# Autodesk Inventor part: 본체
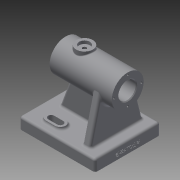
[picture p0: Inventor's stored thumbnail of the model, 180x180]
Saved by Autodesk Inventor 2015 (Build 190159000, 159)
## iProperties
Created: 2022-06
Part Number: 본체
Material: 일반
Document SubType Name: Modeling
Designer: 104658
Density: 1 g/cm^3
Appearance: 기본값
Author: 104658
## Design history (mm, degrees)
sketch "스케치1"
  geometry: L1 (-50, -43)-(50, -43); L2 (50, -43)-(50, 43); L3 (50, 43)-(-50, 43); L4 (-50, 43)-(-50, -43); L5 (-50, -43)-(50, 43); L6 (50, -43)-(-50, 43); 1 further point
  constraints: 12 end point, 2 midpoint, 2 parallel, 1 horizontal, 1 perpendicular
  dimensions: "d0" = 100 distance of L2.end L3.end; "d1" = 86 distance of L1.end L2.end
extrude "돌출1" new body sketch "스케치1" distance "d2" = 15; taper "d3" = 0 deg
sketch "스케치2"
  geometry: L1 (-50, -43)-(50, -43) reference; L2 (50, -43)-(50, 43) reference; L3 (50, 43)-(-50, 43) reference; L4 (-50, 43)-(-50, -43) reference; L5 (25, -35)-(35, -35); L6 (35, -35)-(35, 35); L7 (35, 35)-(25, 35); L8 (25, 35)-(25, -35); L9 (25, -35)-(35, 35); L10 (35, -35)-(25, 35); L11 (-35, -5)-(35, -5); L12 (35, -5)-(35, 5); L13 (35, 5)-(-35, 5); L14 (-35, 5)-(-35, -5); L15 (-35, -5)-(35, 5); L16 (35, -5)-(-35, 5); 3 further points
  constraints: 24 end point, 4 midpoint, 4 parallel, 2 horizontal, 2 perpendicular, 1 point on line
  dimensions: "d4" = 15 distance between parallel lines of L2 L6; "d5" = 10 distance of L6.end L7.end; "d6" = 10 distance of L13.end L11.start; "d7" = 43 distance from line of L1 point (0, 0); "d8" = 15 distance between parallel lines of L4 L14; "d9" = 8 distance between parallel lines of L1 L5; "d10" = 8 distance between parallel lines of L3 L7
extrude "돌출2" join sketch "스케치2" distance "d11" = 57; taper "d12" = 0 deg
feature "면 기울기1" dims angle "d13" = 20 deg
sketch "스케치3"
  geometry: L1 (-50, 0)-(-50, 15) reference; L2 (-50, 15)-(-35, 15) reference; L3 (-35, 15)-(-35, 72) reference; L4 (-35, 72)-(14.254, 72) reference; L5 (14.254, 72)-(35, 15) reference; L6 (35, 15)-(50, 15) reference; L7 (50, 15)-(50, 0) reference; L8 (50, 0)-(-50, 0) reference; L9 (-50, 93)-(32, 93); L10 (32, 93)-(32, 72); L11 (32, 72)-(-50, 72); L12 (-50, 72)-(-50, 93); 1 further point
  constraints: 8 end point, 2 parallel, 1 collinear, 1 horizontal, 1 perpendicular, 1 vertical alignment
  dimensions: "d14" = 21 distance of L11.end L9.start; "d15" = 82 distance of L9.start L9.end
revolve "회전1" sketch "스케치3" stored, may be unused: angle "d16" = 90 deg
sketch "스케치4"
  geometry: L1 (-57, 0)-(-57, 14) reference; L2 (15, -8)-(0, -8) reference; L3 (0, -8)-(0, 0) reference; L4 (0, 0)-(-57, 0) reference; L5 (-57, 0)-(-57, 14) reference; L6 (-57, 56)-(-57, 70) reference; L7 (-57, 70)-(0, 70) reference; L8 (0, 70)-(0, 78) reference; L9 (0, 78)-(15, 78) reference; L10 (15, 78)-(15, -8) reference; L11 (0, 0)-(0, 70) reference; L12 (-57, 14)-(0, 0); L13 (-57, 56)-(0, 70); A1 r 21 centre (-57, 35) between (-57, 14) and (-57, 56) reference; A2 r 21 centre (-57, 35) between (-57, 56) and (-57, 14) reference; 1 further point
  constraints: 4 end point
extrude "돌출3" cut sketch "스케치4" stored distance "d17" = 57; taper "d18" = 0 deg
sketch "스케치5"
  geometry: C1 r 21 at (0, 0) reference; 1 further point
hole "구멍1" sketch "스케치5" at (0, 0) diameter "d19" = 23; stored, may be unused: countersink angle "d23" = 90 deg, drill point angle "d25" = 118 deg; dims "d20" = 6, "d21" = 29, "d22" = 62, "d24" = 8
node "작업 평면1"
sketch "스케치6"
  geometry: L1 (32, -21)-(32, 21) reference; C1 r 11 at (7, 0); 1 further point
  constraints: 1 centre point, 1 horizontal alignment
  dimensions: "d27" = 25 distance from line of C1.centre L1; "d28" = 22 diameter of C1
extrude "돌출4" join sketch "스케치6" stored distance "d29" = 57; taper "d30" = 0 deg
sketch "스케치7"
  geometry: C1 r 11 at (0, 0) reference; 1 further point
hole "구멍2" sketch "스케치7" at (0, 0) diameter "d31" = 4.917; stored, may be unused: countersink angle "d35" = 90 deg, drill point angle "d37" = 0 deg; dims "d32" = 12, "d33" = 14, "d34" = 4, "d36" = 17.1
sketch "스케치8"
  geometry: C1 r 11.5 at (0, 0) reference; 2 further points
  constraints: 1 horizontal alignment
  dimensions: "d38" = 18 distance of C1.centre point (-18, 0)
hole "구멍3" sketch "스케치8" at (-18, 0) diameter "d39" = 2.459; stored, may be unused: countersink angle "d43" = 90 deg, drill point angle "d45" = 118 deg; dims "d40" = 8, "d41" = 14, "d42" = 4, "d44" = 10
sketch "스케치9"
  geometry: C1 r 14.5 at (0, 0) reference; 2 further points
  constraints: 1 horizontal alignment
  dimensions: "d49" = 18 distance of C1.centre point (18, 0)
hole "구멍4" sketch "스케치9" at (18, 0) diameter "d50" = 2.459; stored, may be unused: countersink angle "d54" = 90 deg, drill point angle "d56" = 118 deg; dims "d51" = 8, "d52" = 14, "d53" = 4, "d55" = 10
sketch "스케치10"
  geometry: L1 (-50, 43)-(-50, -43) reference; L2 (50, 43)-(-50, 43) reference; L3 (-24, 27)-(-12, 27); L4 (-24, 20)-(-12, 20); L5 (-12, 34)-(-24, 34); A1 r 7 centre (-24, 27) between (-24, 34) and (-24, 20); A2 r 7 centre (-12, 27) between (-12, 20) and (-12, 34); 2 further points
  constraints: 8 end point, 4 point on circle, 4 tangent, 2 centre point, 1 horizontal, 1 midpoint, 1 parallel
  dimensions: "d60" = 12 distance of L3.end L3.start; "d61" = 26 distance from line of L1 L3.start; "d62" = 16 distance from line of L2 L3.start; "d64" = 14 distance between parallel lines of L4 L5
extrude "돌출5" join sketch "스케치10" distance "d65" = 3; taper "d66" = 0 deg
sketch "스케치11"
  geometry: L1 (-12, 27)-(-24, 27); L2 (-12, 31)-(-24, 31); L3 (-24, 23)-(-12, 23); A1 r 7 centre (-12, 27) between (-12, 20) and (-12, 34) reference; A2 r 7 centre (-24, 27) between (-24, 34) and (-24, 20) reference; A3 r 4 centre (-12, 27) between (-12, 23) and (-12, 31); A4 r 4 centre (-24, 27) between (-24, 31) and (-24, 23); 2 further points
  constraints: 8 end point, 4 point on circle, 4 tangent, 2 centre point, 1 horizontal, 1 midpoint, 1 parallel
  dimensions: "d68" = 8 distance between parallel lines of L2 L3
extrude "돌출6" cut sketch "스케치11" stored distance "d69" = 3; taper "d70" = 0 deg
fillet "모깎기1" dims "d71" = 3
fillet "모깎기2" dims "d72" = 3
fillet "모깎기3" dims "d73" = 3
fillet "모깎기4" dims "d74" = 3
fillet "모깎기5" dims "d75" = 3
fillet "모깎기6" dims "d76" = 1
fillet "모깎기7" dims "d77" = 3
sketch "스케치12"
  geometry: L1 (0, 0)-(0, 80) reference; 3 further points
  constraints: 1 horizontal alignment, 1 midpoint, 1 other
  dimensions: "d78" = 6 distance from line of point (-6, 40) L1
feature "엠보싱1" sketch "스케치12" dims "d0" = 100, "d1" = 86, "d4" = 15, "d5" = 10, "d6" = 10, "d7" = 43, "d8" = 15, "d9" = 8, "d10" = 8, "d79" = 0.5, "d80" = 0
chamfer "모따기1" distance "d81" = 1; stored, may be unused: second distance "d82" = 2, angle "d83" = 45 deg
chamfer "모따기2" distance "d84" = 1; stored, may be unused: second distance "d85" = 2, angle "d86" = 45 deg
node "솔리드1"
pattern_circular "원형 패턴1" dims angle "d47" = 360 deg
pattern_circular "원형 패턴2" dims angle "d58" = 360 deg
mirror "대칭1"
node "절단 모서리 투영1"
node "절단 모서리 투영2"
other parameters: "d26" = -96
